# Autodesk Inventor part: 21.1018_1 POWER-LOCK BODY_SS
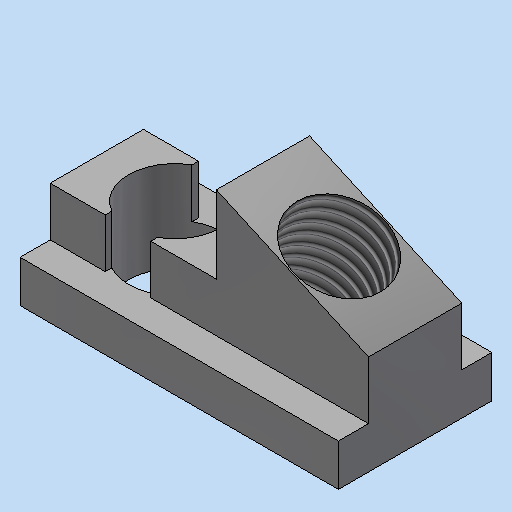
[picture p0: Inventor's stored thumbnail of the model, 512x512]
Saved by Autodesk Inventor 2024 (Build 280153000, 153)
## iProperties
Created: 2006-12
Part Number: 21.1018_1 POWER-LOCK BODY_SS
Document SubType Name: Modeling
Designer: Andy Moles
Material: Stainless Steel
Density: 8.08 g/cm^3
Mass: 13.9701 g
Surface Area: 18.0778 cm^2
Volume: 1.72898 cm^3
Appearance: Steel
Author: Andy Moles
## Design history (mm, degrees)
sketch "Sketch3"
  geometry: L1 (-14, 0)-(14, 0); L2 (-14, 0)-(-14, 8); L3 (14, 0)-(14, 8.763); L4 (14, 8.763)-(0.614, 14.808); L5 (-14, 8)-(0.614, 8); L6 (0.614, 14.808)-(0.614, 8); 2 further points
  constraints: 12 end point, 2 horizontal, 2 perpendicular, 1 coincident, 1 midpoint, 1 parallel
  dimensions: "d2" = 28 distance of L1.start L1.end; "d3" = 8 distance of L1.start L2.end; "d4" = 8.763 distance of L1.end L3.end; "d5" = 13.3858 horizontal distance of L3.end L4.end; "d6" = 14.8082 distance from line of L4.end L1
extrude "Extrusion1" new body sketch "Sketch3" stored distance "d7" = 13.5; taper "d8" = 0 deg
sketch "Sketch4"
  geometry: L1 (-14, 0)-(-14, 8) reference; L2 (14, 0)-(-14, 0) reference; L3 (14, 8.763)-(14, 0) reference; L4 (0.614, 14.808)-(14, 8.763) reference; L5 (0.614, 8)-(0.614, 14.808) reference; L6 (-14, 8)-(0.614, 8) reference; L7 (-14, 3.683)-(14, 3.683); 1 further point
  constraints: 2 end point, 2 point on line, 1 perpendicular
  dimensions: "d9" = 3.683 distance between parallel lines of L7 L2
extrude "Extrusion2" cut sketch "Sketch4" distance "d10" = 2.65; taper "d11" = 0 deg
mirror "Mirror1"
sketch "Sketch5"
  geometry: L1 (0, 8.2)-(0, 0) reference; C1 r 4.05 at (6.844, 4.1); 2 further points
  constraints: 1 centre point, 1 horizontal alignment, 1 midpoint
  dimensions: "d12" = 8.1 diameter of C1; "d13" = 2.794 distance edge to line of C1 L1
extrude "Extrusion3" cut sketch "Sketch5" extent not by distance; stored distance "d14" = 2; taper "d15" = 0 deg
sketch "Sketch6"
  geometry: L1 (-14, 3.683)-(14, 3.683) reference; L2 (-3.106, 0)-(-11.206, 0) reference; L3 (-11.206, 8)-(-3.106, 8) reference; L4 (-9.156, 3.683)-(-5.156, 3.683); L5 (-5.156, 3.683)-(-5.156, 8); L6 (-5.156, 8)-(-9.156, 8); L7 (-9.156, 8)-(-9.156, 3.683); L8 (-5.156, 3.683)-(-9.156, 8); 3 further points
  constraints: 10 end point, 2 midpoint, 2 parallel, 1 collinear, 1 horizontal, 1 perpendicular, 1 point on line, 1 vertical alignment
  dimensions: "d16" = 4 distance between parallel lines of L5 L7
extrude "Extrusion4" cut sketch "Sketch6" extent not by distance; stored distance "d17" = 2; taper "d18" = 0 deg
sketch "Sketch7"
  geometry: L1 (0, 0)-(14.688, 8.2); C1 r 4 at (7.344, 4.1); 1 further point
  constraints: 2 end point, 1 centre point, 1 midpoint
  dimensions: "d19" = 8 diameter of C1
extrude "Extrusion5" cut sketch "Sketch7" extent not by distance; stored distance "d20" = 2; taper "d21" = 0 deg
thread "Thread2" dims "d22" = 10, "d23" = 0
body "Solid1"
node "Projected Loop3"
